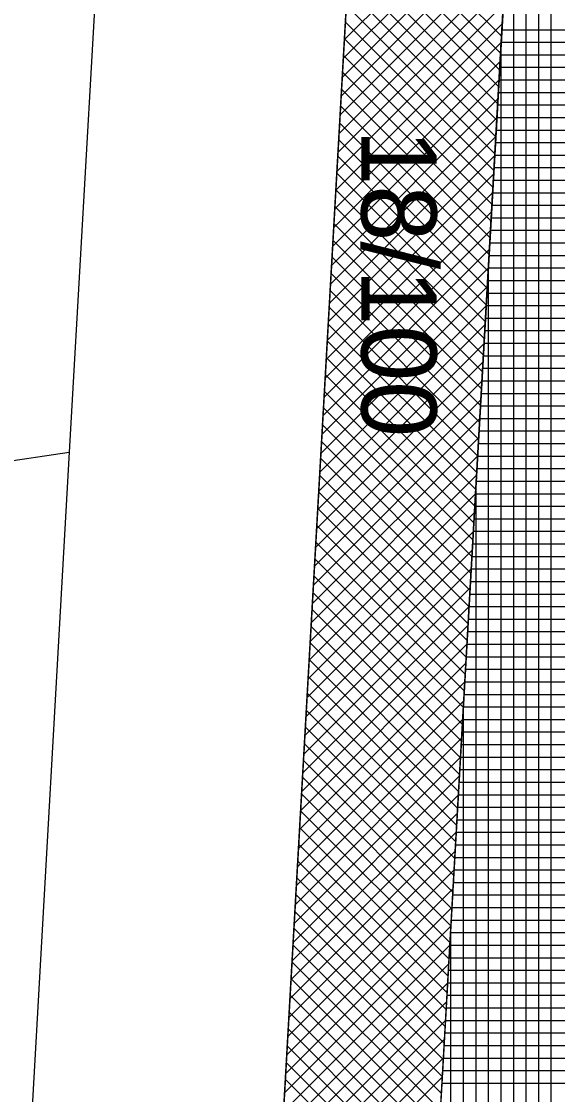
# Model space of a CAD drawing. Extents: x -565346 to -564154, y -1097386 to -1095620.
# Drawn here: x -564297.24 to -564288.69, y -1097074.77 to -1097057.66 of the extents above; entities that cross this region are included whole.
import ezdxf

# ---------------------------------------------------------------- set-up
doc = ezdxf.new("R2010")
doc.units = 0
for name, color, linetype in [('Vrstva 1', 7, 'Continuous'), ('Vrstva 40', 7, 'Continuous'), ('Vrstva 41', 7, 'Continuous'), ('Vrstva 42', 7, 'Continuous'), ('Vrstva 43', 7, 'Continuous')]:
    doc.layers.add(name, color=color, linetype=linetype)

msp = doc.modelspace()

# ---------------------------------------------------------------- linework, layer by layer
at = {"layer": 'Vrstva 1'}
for p, q in [((-564296.5, -1097135.53), (-564285.9, -1096948.97)), ((-564291.89, -1096983.76), (-564296.48, -1097064.53)), ((-564456.068, -1097087.738), (-564296.48, -1097064.53)), ((-564296.48, -1097064.53), (-564302.81, -1097176.11))]:
    msp.add_line(p, q, dxfattribs=at)
at = {"layer": 'Vrstva 41'}
msp.add_lwpolyline([(-564296.782, -1097140.492), (-564294.286, -1097140.634), (-564282.373, -1096930.972), (-564284.87, -1096930.83)], close=True, dxfattribs=at)
at = {"layer": 'Vrstva 42'}
for p, q in [((-564289.437, -1097055.296), (-564292.092, -1097057.951)), ((-564289.454, -1097055.596), (-564292.109, -1097058.251)), ((-564291.955, -1097055.526), (-564289.585, -1097057.895)), ((-564291.97, -1097055.793), (-564289.6, -1097058.163)), ((-564289.471, -1097055.895), (-564292.126, -1097058.551)), ((-564291.985, -1097056.061), (-564289.615, -1097058.431)), ((-564289.488, -1097056.195), (-564292.143, -1097058.851)), ((-564292, -1097056.329), (-564289.63, -1097058.698)), ((-564289.505, -1097056.495), (-564292.16, -1097059.15)), ((-564292.015, -1097056.596), (-564289.646, -1097058.966)), ((-564289.522, -1097056.795), (-564292.178, -1097059.45)), ((-564292.031, -1097056.864), (-564289.661, -1097059.234)), ((-564289.539, -1097057.095), (-564292.195, -1097059.75)), ((-564292.046, -1097057.132), (-564289.676, -1097059.501)), ((-564289.556, -1097057.395), (-564292.212, -1097060.05)), ((-564292.061, -1097057.399), (-564289.691, -1097059.769)), ((-564289.573, -1097057.695), (-564292.229, -1097060.35)), ((-564292.076, -1097057.667), (-564289.706, -1097060.037)), ((-564289.59, -1097057.995), (-564292.246, -1097060.65)), ((-564292.091, -1097057.934), (-564289.722, -1097060.304)), ((-564292.107, -1097058.202), (-564289.737, -1097060.572)), ((-564289.607, -1097058.295), (-564292.263, -1097060.95)), ((-564292.122, -1097058.47), (-564289.752, -1097060.839)), ((-564289.625, -1097058.594), (-564292.28, -1097061.25)), ((-564292.137, -1097058.737), (-564289.767, -1097061.107)), ((-564289.642, -1097058.894), (-564292.297, -1097061.55)), ((-564292.152, -1097059.005), (-564289.782, -1097061.375)), ((-564289.659, -1097059.194), (-564292.314, -1097061.849)), ((-564292.167, -1097059.273), (-564289.798, -1097061.642)), ((-564289.676, -1097059.494), (-564292.331, -1097062.149)), ((-564292.183, -1097059.54), (-564289.813, -1097061.91)), ((-564289.693, -1097059.794), (-564292.348, -1097062.449)), ((-564292.198, -1097059.808), (-564289.828, -1097062.178)), ((-564289.71, -1097060.094), (-564292.365, -1097062.749)), ((-564292.213, -1097060.076), (-564289.843, -1097062.445)), ((-564289.727, -1097060.394), (-564292.382, -1097063.049)), ((-564292.228, -1097060.343), (-564289.859, -1097062.713)), ((-564292.243, -1097060.611), (-564289.874, -1097062.981)), ((-564289.744, -1097060.694), (-564292.399, -1097063.349)), ((-564292.259, -1097060.879), (-564289.889, -1097063.248)), ((-564289.761, -1097060.993), (-564292.416, -1097063.649)), ((-564289.778, -1097061.293), (-564292.433, -1097063.949)), ((-564292.274, -1097061.146), (-564289.904, -1097063.516)), ((-564292.289, -1097061.414), (-564289.919, -1097063.783)), ((-564289.795, -1097061.593), (-564292.45, -1097064.248)), ((-564292.304, -1097061.681), (-564289.935, -1097064.051)), ((-564289.812, -1097061.893), (-564292.467, -1097064.548)), ((-564292.319, -1097061.949), (-564289.95, -1097064.319)), ((-564289.829, -1097062.193), (-564292.484, -1097064.848)), ((-564292.335, -1097062.217), (-564289.965, -1097064.586)), ((-564289.846, -1097062.493), (-564292.501, -1097065.148)), ((-564292.35, -1097062.484), (-564289.98, -1097064.854)), ((-564289.863, -1097062.793), (-564292.518, -1097065.448)), ((-564292.365, -1097062.752), (-564289.995, -1097065.122)), ((-564289.88, -1097063.093), (-564292.535, -1097065.748)), ((-564292.38, -1097063.02), (-564290.011, -1097065.389)), ((-564292.395, -1097063.287), (-564290.026, -1097065.657)), ((-564289.897, -1097063.393), (-564292.552, -1097066.048)), ((-564289.914, -1097063.692), (-564292.569, -1097066.348)), ((-564292.411, -1097063.555), (-564290.041, -1097065.925)), ((-564292.426, -1097063.823), (-564290.056, -1097066.192)), ((-564289.931, -1097063.992), (-564292.586, -1097066.647)), ((-564292.441, -1097064.09), (-564290.071, -1097066.46)), ((-564289.948, -1097064.292), (-564292.603, -1097066.947)), ((-564292.456, -1097064.358), (-564290.087, -1097066.727)), ((-564289.965, -1097064.592), (-564292.62, -1097067.247)), ((-564292.472, -1097064.625), (-564290.102, -1097066.995)), ((-564289.982, -1097064.892), (-564292.638, -1097067.547)), ((-564292.487, -1097064.893), (-564290.117, -1097067.263)), ((-564289.999, -1097065.192), (-564292.655, -1097067.847)), ((-564292.502, -1097065.161), (-564290.132, -1097067.53)), ((-564290.016, -1097065.492), (-564292.672, -1097068.147)), ((-564292.517, -1097065.428), (-564290.147, -1097067.798)), ((-564292.532, -1097065.696), (-564290.163, -1097068.066)), ((-564290.033, -1097065.792), (-564292.689, -1097068.447)), ((-564290.05, -1097066.091), (-564292.706, -1097068.747)), ((-564292.548, -1097065.964), (-564290.178, -1097068.333)), ((-564292.563, -1097066.231), (-564290.193, -1097068.601)), ((-564290.068, -1097066.391), (-564292.723, -1097069.047)), ((-564292.578, -1097066.499), (-564290.208, -1097068.869)), ((-564290.085, -1097066.691), (-564292.74, -1097069.346)), ((-564292.593, -1097066.767), (-564290.223, -1097069.136)), ((-564290.102, -1097066.991), (-564292.757, -1097069.646)), ((-564292.608, -1097067.034), (-564290.239, -1097069.404)), ((-564290.119, -1097067.291), (-564292.774, -1097069.946)), ((-564292.624, -1097067.302), (-564290.254, -1097069.671)), ((-564290.136, -1097067.591), (-564292.791, -1097070.246)), ((-564292.639, -1097067.569), (-564290.269, -1097069.939)), ((-564290.153, -1097067.891), (-564292.808, -1097070.546)), ((-564292.654, -1097067.837), (-564290.284, -1097070.207)), ((-564292.669, -1097068.105), (-564290.3, -1097070.474)), ((-564290.17, -1097068.191), (-564292.825, -1097070.846)), ((-564290.187, -1097068.491), (-564292.842, -1097071.146)), ((-564292.684, -1097068.372), (-564290.315, -1097070.742)), ((-564292.7, -1097068.64), (-564290.33, -1097071.01)), ((-564290.204, -1097068.79), (-564292.859, -1097071.446)), ((-564292.715, -1097068.908), (-564290.345, -1097071.277)), ((-564290.221, -1097069.09), (-564292.876, -1097071.745)), ((-564292.73, -1097069.175), (-564290.36, -1097071.545)), ((-564290.238, -1097069.39), (-564292.893, -1097072.045)), ((-564292.745, -1097069.443), (-564290.376, -1097071.813)), ((-564290.255, -1097069.69), (-564292.91, -1097072.345)), ((-564292.76, -1097069.711), (-564290.391, -1097072.08)), ((-564290.272, -1097069.99), (-564292.927, -1097072.645)), ((-564292.776, -1097069.978), (-564290.406, -1097072.348)), ((-564290.289, -1097070.29), (-564292.944, -1097072.945)), ((-564292.791, -1097070.246), (-564290.421, -1097072.615)), ((-564292.806, -1097070.513), (-564290.436, -1097072.883)), ((-564290.306, -1097070.59), (-564292.961, -1097073.245)), ((-564292.821, -1097070.781), (-564290.452, -1097073.151)), ((-564290.323, -1097070.89), (-564292.978, -1097073.545)), ((-564292.836, -1097071.049), (-564290.467, -1097073.418)), ((-564290.34, -1097071.189), (-564292.995, -1097073.845)), ((-564292.852, -1097071.316), (-564290.482, -1097073.686)), ((-564290.357, -1097071.489), (-564293.012, -1097074.144)), ((-564292.867, -1097071.584), (-564290.497, -1097073.954)), ((-564290.374, -1097071.789), (-564293.029, -1097074.444)), ((-564292.882, -1097071.852), (-564290.512, -1097074.221)), ((-564290.391, -1097072.089), (-564293.046, -1097074.744)), ((-564292.897, -1097072.119), (-564290.528, -1097074.489)), ((-564290.408, -1097072.389), (-564293.063, -1097075.044)), ((-564292.912, -1097072.387), (-564290.543, -1097074.757)), ((-564290.425, -1097072.689), (-564293.08, -1097075.344)), ((-564292.928, -1097072.655), (-564290.558, -1097075.024)), ((-564292.943, -1097072.922), (-564290.573, -1097075.292)), ((-564290.442, -1097072.989), (-564293.097, -1097075.644)), ((-564292.958, -1097073.19), (-564290.588, -1097075.559)), ((-564290.459, -1097073.289), (-564293.115, -1097075.944)), ((-564290.476, -1097073.589), (-564293.132, -1097076.244)), ((-564292.973, -1097073.457), (-564290.604, -1097075.827)), ((-564292.988, -1097073.725), (-564290.619, -1097076.095)), ((-564290.494, -1097073.888), (-564293.149, -1097076.544)), ((-564293.004, -1097073.993), (-564290.634, -1097076.362)), ((-564290.511, -1097074.188), (-564293.166, -1097076.843)), ((-564293.019, -1097074.26), (-564290.649, -1097076.63)), ((-564290.528, -1097074.488), (-564293.183, -1097077.143)), ((-564293.034, -1097074.528), (-564290.664, -1097076.898))]:
    msp.add_line(p, q, dxfattribs=at)
at = {"layer": 'Vrstva 43'}
for p, q in [((-564288.79, -1097176.246), (-564288.79, -1097043.908)), ((-564288.99, -1097179.766), (-564288.99, -1097047.427)), ((-564289.19, -1097183.288), (-564289.19, -1097050.947)), ((-564289.39, -1097186.812), (-564289.39, -1097054.467)), ((-564289.579, -1097057.79), (-564282.064, -1097057.79)), ((-564289.59, -1097190.335), (-564289.59, -1097057.987)), ((-564289.59, -1097057.99), (-564282.075, -1097057.99)), ((-564289.602, -1097058.19), (-564282.086, -1097058.19)), ((-564289.613, -1097058.39), (-564282.098, -1097058.39)), ((-564289.624, -1097058.59), (-564282.109, -1097058.59)), ((-564289.636, -1097058.79), (-564282.12, -1097058.79)), ((-564289.647, -1097058.99), (-564282.132, -1097058.99)), ((-564289.658, -1097059.19), (-564282.143, -1097059.19)), ((-564289.67, -1097059.39), (-564282.154, -1097059.39)), ((-564289.681, -1097059.59), (-564282.166, -1097059.59)), ((-564289.692, -1097059.79), (-564282.177, -1097059.79)), ((-564289.704, -1097059.99), (-564282.189, -1097059.99)), ((-564289.715, -1097060.19), (-564282.2, -1097060.19)), ((-564289.727, -1097060.39), (-564282.211, -1097060.39)), ((-564289.738, -1097060.59), (-564282.223, -1097060.59)), ((-564289.749, -1097060.79), (-564282.234, -1097060.79)), ((-564289.761, -1097060.99), (-564282.245, -1097060.99)), ((-564289.772, -1097061.19), (-564282.257, -1097061.19)), ((-564289.783, -1097061.39), (-564282.268, -1097061.39)), ((-564289.795, -1097061.59), (-564282.279, -1097061.59)), ((-564289.79, -1097193.858), (-564289.79, -1097061.507)), ((-564289.806, -1097061.79), (-564282.291, -1097061.79)), ((-564289.817, -1097061.99), (-564282.302, -1097061.99)), ((-564289.829, -1097062.19), (-564282.313, -1097062.19)), ((-564289.84, -1097062.39), (-564282.325, -1097062.39)), ((-564289.852, -1097062.59), (-564282.336, -1097062.59)), ((-564289.863, -1097062.79), (-564282.347, -1097062.79)), ((-564289.874, -1097062.99), (-564282.359, -1097062.99)), ((-564289.886, -1097063.19), (-564282.37, -1097063.19)), ((-564289.897, -1097063.39), (-564282.382, -1097063.39)), ((-564289.908, -1097063.59), (-564282.393, -1097063.59)), ((-564289.92, -1097063.79), (-564282.404, -1097063.79)), ((-564289.931, -1097063.99), (-564282.416, -1097063.99)), ((-564289.942, -1097064.19), (-564282.427, -1097064.19)), ((-564289.954, -1097064.39), (-564282.438, -1097064.39)), ((-564289.965, -1097064.59), (-564282.45, -1097064.59)), ((-564289.977, -1097064.79), (-564282.461, -1097064.79)), ((-564289.99, -1097197.382), (-564289.99, -1097065.027)), ((-564289.988, -1097064.99), (-564282.472, -1097064.99)), ((-564289.999, -1097065.19), (-564282.484, -1097065.19)), ((-564290.011, -1097065.39), (-564282.495, -1097065.39)), ((-564290.022, -1097065.59), (-564282.506, -1097065.59)), ((-564290.033, -1097065.79), (-564282.518, -1097065.79)), ((-564290.045, -1097065.99), (-564282.529, -1097065.99)), ((-564290.056, -1097066.19), (-564282.541, -1097066.19)), ((-564290.067, -1097066.39), (-564282.552, -1097066.39)), ((-564290.079, -1097066.59), (-564282.563, -1097066.59)), ((-564290.09, -1097066.79), (-564282.575, -1097066.79)), ((-564290.102, -1097066.99), (-564282.586, -1097066.99)), ((-564290.113, -1097067.19), (-564282.597, -1097067.19)), ((-564290.124, -1097067.39), (-564282.609, -1097067.39)), ((-564290.136, -1097067.59), (-564282.62, -1097067.59)), ((-564290.147, -1097067.79), (-564282.631, -1097067.79)), ((-564290.158, -1097067.99), (-564282.643, -1097067.99)), ((-564290.17, -1097068.19), (-564282.654, -1097068.19)), ((-564290.181, -1097068.39), (-564282.665, -1097068.39)), ((-564290.192, -1097068.59), (-564282.677, -1097068.59)), ((-564290.19, -1097200.905), (-564290.19, -1097068.547)), ((-564290.204, -1097068.79), (-564282.688, -1097068.79)), ((-564290.215, -1097068.99), (-564282.699, -1097068.99)), ((-564290.227, -1097069.19), (-564282.711, -1097069.19)), ((-564290.238, -1097069.39), (-564282.722, -1097069.39)), ((-564290.249, -1097069.59), (-564282.734, -1097069.59)), ((-564290.261, -1097069.79), (-564282.745, -1097069.79)), ((-564290.272, -1097069.99), (-564282.756, -1097069.99)), ((-564290.283, -1097070.19), (-564282.768, -1097070.19)), ((-564290.295, -1097070.39), (-564282.779, -1097070.39)), ((-564290.306, -1097070.59), (-564282.79, -1097070.59)), ((-564290.317, -1097070.79), (-564282.802, -1097070.79)), ((-564290.329, -1097070.99), (-564282.813, -1097070.99)), ((-564290.34, -1097071.19), (-564282.824, -1097071.19)), ((-564290.352, -1097071.39), (-564282.836, -1097071.39)), ((-564290.363, -1097071.59), (-564282.847, -1097071.59)), ((-564290.374, -1097071.79), (-564282.858, -1097071.79)), ((-564290.39, -1097204.428), (-564290.39, -1097072.067)), ((-564290.386, -1097071.99), (-564282.87, -1097071.99)), ((-564290.397, -1097072.19), (-564282.881, -1097072.19)), ((-564290.408, -1097072.39), (-564282.892, -1097072.39)), ((-564290.42, -1097072.59), (-564282.904, -1097072.59)), ((-564290.431, -1097072.79), (-564282.915, -1097072.79)), ((-564290.442, -1097072.99), (-564282.927, -1097072.99)), ((-564290.454, -1097073.19), (-564282.938, -1097073.19)), ((-564290.465, -1097073.39), (-564282.949, -1097073.39)), ((-564290.477, -1097073.59), (-564282.961, -1097073.59)), ((-564290.488, -1097073.79), (-564282.972, -1097073.79)), ((-564290.499, -1097073.99), (-564282.983, -1097073.99)), ((-564290.511, -1097074.19), (-564282.995, -1097074.19)), ((-564290.522, -1097074.39), (-564283.006, -1097074.39)), ((-564290.533, -1097074.59), (-564283.017, -1097074.59))]:
    msp.add_line(p, q, dxfattribs=at)
msp.add_lwpolyline([(-564283.37, -1096906.18), (-564284.87, -1096930.83), (-564282.373, -1096930.972), (-564294.286, -1097140.634), (-564296.782, -1097140.492), (-564297.42, -1097150.37), (-564294.347, -1097150.646), (-564303.226, -1097307.04), (-564304.096, -1097322.37), (-564304.399, -1097332.838), (-564302.848, -1097333.175), (-564297.082, -1097322.329), (-564293.197, -1097253.877), (-564289.027, -1097180.417), (-564287.358, -1097151.043), (-564285.364, -1097151.156), (-564284.798, -1097141.172), (-564286.791, -1097141.059), (-564274.888, -1096931.397), (-564272.899, -1096931.51), (-564271.475, -1096906.55)], dxfattribs=at)

# ---------------------------------------------------------------- texts
at = {"layer": 'Vrstva 40'}
msp.add_text('18/100', height=1.2, rotation=270, dxfattribs=at).set_placement((-564291.82, -1097059.38))

doc.saveas('drawing.dxf')
